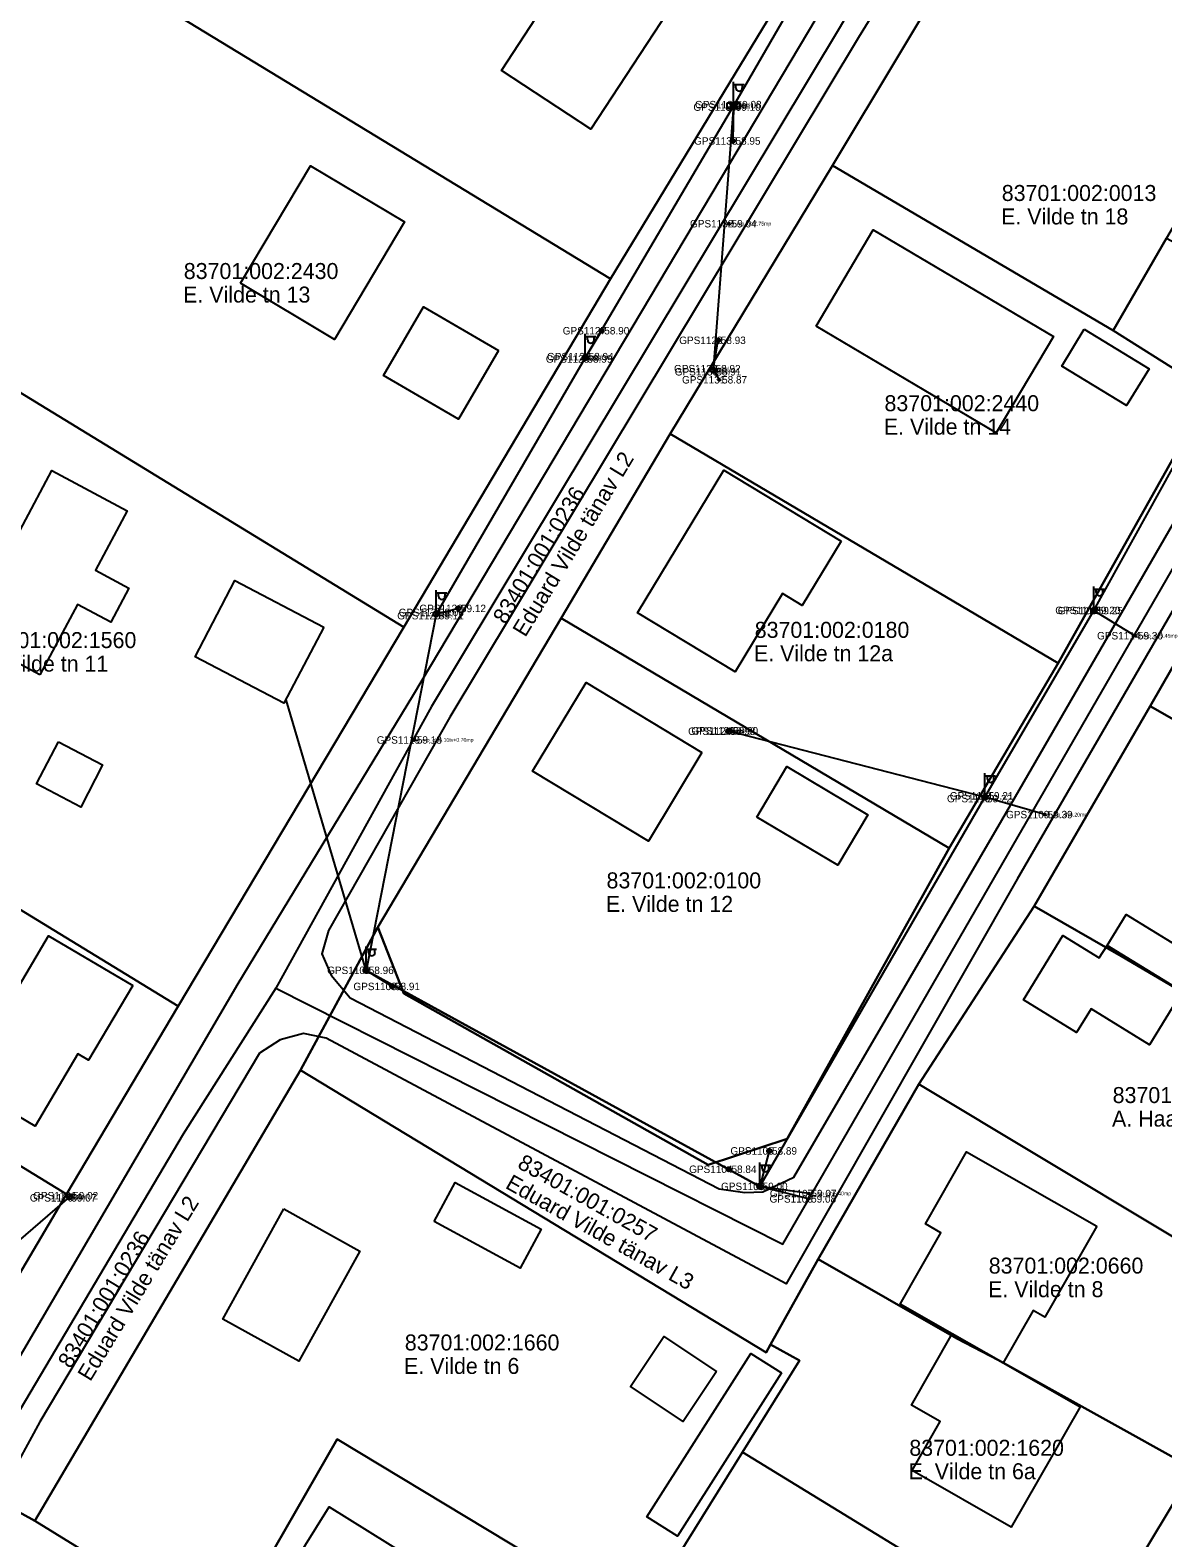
# Model space of a CAD drawing. Extents: x 580119 to 583377, y 6518915 to 6520820.
# Drawn here: x 581695.9 to 581802.2, y 6520085.2 to 6520226.6 of the extents above; entities that cross this region are included whole.
import ezdxf

# ---------------------------------------------------------------- set-up
doc = ezdxf.new("R2010")
doc.units = 0
for name, color, linetype in [('ELRAJATISMP', 7, 'Continuous'), ('Hoone Elu- või ühiskondlik hoone', 7, 'Continuous'), ('Hoone Kõrval- või tootmishoone', 7, 'Continuous'), ('L_AADRESS', 7, 'Continuous'), ('MAAMUDEL', 7, 'Continuous'), ('MOOTKORG-EH2000', 7, 'Continuous'), ('MOOTMPUNKT', 7, 'Continuous'), ('MOOTNR', 7, 'Continuous'), ('MPOHULIIN', 7, 'Continuous'), ('Muu rajatis Katusealune', 7, 'Continuous'), ('PIIR', 7, 'Continuous'), ('POST', 7, 'Continuous'), ('Rippe kõrgus', 7, 'Continuous'), ('SIOHULIIN', 7, 'Continuous'), ('Tee Liiklusala', 7, 'Continuous'), ('Tee Tänav Püsikate', 7, 'Continuous'), ('TUNNUS', 7, 'Continuous')]:
    doc.layers.add(name, color=color, linetype=linetype)

msp = doc.modelspace()

# ---------------------------------------------------------------- linework, layer by layer
at = {"layer": 'ELRAJATISMP'}
for p, q in [((581761.76, 6520219.8), (581761.76, 6520219.21)), ((581762.03, 6520219.8), (581762.03, 6520219.21))]:
    msp.add_line(p, q, dxfattribs=at)
msp.add_lwpolyline([(581761.3, 6520219.8), (581762.5, 6520219.8), (581762.5, 6520219.21), (581761.3, 6520219.21)], close=True, dxfattribs=at)
at = {"layer": 'Hoone Elu- või ühiskondlik hoone'}
for points in [[(581749.32, 6520236.85), (581757.72, 6520231.36), (581748.53, 6520217.33), (581740.14, 6520222.82)], [(581715.66, 6520202.86), (581722.22, 6520213.88), (581731.05, 6520208.63), (581724.5, 6520197.6)], [(581769.66, 6520198.84), (581775.02, 6520207.88), (581791.91, 6520197.86), (581786.55, 6520188.82)], [(581739.87, 6520196.57), (581736.13, 6520190.12), (581729.09, 6520194.21), (581732.84, 6520200.65)], [(581696.86, 6520166.14), (581689.77, 6520169.92), (581697.96, 6520185.31), (581705.05, 6520181.53), (581702.07, 6520175.94), (581705.21, 6520174.27), (581703.51, 6520171.07), (581700.37, 6520172.74)], [(581772.01, 6520178.68), (581768.36, 6520172.63), (581766.51, 6520173.75), (581762.06, 6520166.41), (581752.91, 6520171.95), (581761.01, 6520185.33)], [(581723.47, 6520170.61), (581719.74, 6520163.47), (581711.41, 6520167.83), (581715.14, 6520174.97)], [(581758.95, 6520158.83), (581753.93, 6520150.52), (581743.06, 6520157.09), (581748.09, 6520165.4)], [(581705.56, 6520137), (581701.42, 6520129.98), (581700.4, 6520130.59), (581696.4, 6520123.79), (581688.08, 6520128.69), (581692.34, 6520135.89), (581693.77, 6520135.04), (581697.67, 6520141.65)], [(581795.98, 6520114.4), (581791.1, 6520105.88), (581790, 6520106.5), (581787.19, 6520101.59), (581782.43, 6520104.31), (581777.55, 6520107.1), (581781.37, 6520113.8), (581779.91, 6520114.64), (581783.77, 6520121.38)], [(581719.72, 6520116.03), (581726.86, 6520112.07), (581721.14, 6520101.74), (581714, 6520105.7)], [(581787.19, 6520101.59), (581794.41, 6520097.46), (581787.96, 6520086.18), (581778.67, 6520091.5), (581781.3, 6520096.08), (581778.6, 6520097.63), (581782.43, 6520104.31)], [(581718.35, 6520079.05), (581723.97, 6520088.07), (581737.07, 6520079.91), (581731.45, 6520070.89)]]:
    msp.add_lwpolyline(points, close=True, dxfattribs=at)
at = {"layer": 'Hoone Kõrval- või tootmishoone'}
for points in [[(581794.81, 6520198.55), (581800.89, 6520194.85), (581798.78, 6520191.38), (581792.7, 6520195.08)], [(581764.1, 6520152.79), (581766.91, 6520157.52), (581774.51, 6520153), (581771.7, 6520148.26)], [(581803.99, 6520136.42), (581796.95, 6520140.75), (581798.73, 6520143.64), (581805.77, 6520139.32)], [(581796.95, 6520140.75), (581803.99, 6520136.42), (581800.92, 6520131.43), (581795.45, 6520134.79), (581794.09, 6520132.57), (581789.1, 6520135.64), (581792.8, 6520141.67), (581796.22, 6520139.57)], [(581733.83, 6520114.86), (581735.81, 6520118.5), (581743.87, 6520114.12), (581741.89, 6520110.48)], [(581760.31, 6520100.78), (581757.18, 6520096.08), (581752.24, 6520099.36), (581755.37, 6520104.07)], [(581766.41, 6520100.65), (581756.65, 6520085.34), (581753.77, 6520087.15), (581763.53, 6520102.47)]]:
    msp.add_lwpolyline(points, close=True, dxfattribs=at)
at = {"layer": 'MOOTMPUNKT'}
for centre in [(581761.86, 6520219.39), (581761.94, 6520219.62), (581761.84, 6520216.21), (581761.47, 6520208.45), (581749.53, 6520198.41), (581760.46, 6520197.51), (581747.95, 6520195.76), (581748.06, 6520195.98), (581759.97, 6520194.85), (581760.04, 6520194.56), (581760.58, 6520193.81), (581736.09, 6520172.36), (581795.59, 6520172.18), (581795.82, 6520172.15), (581734.01, 6520171.98), (581734.01, 6520171.68), (581799.58, 6520169.8), (581761.36, 6520160.84), (581761.61, 6520160.88), (581731.95, 6520160.02), (581785.43, 6520154.52), (581785.56, 6520154.78), (581791.11, 6520153.02), (581727.44, 6520138.41), (581729.9, 6520136.9), (581765.26, 6520121.47), (581761.46, 6520119.75), (581699.55, 6520117.07), (581699.72, 6520117.27), (581764.38, 6520118.14), (581768.93, 6520116.97), (581768.96, 6520117.47)]:
    msp.add_circle(centre, 0.1, dxfattribs=at)
at = {"layer": 'MPOHULIIN'}
for p, q in [((581795.71, 6520172.16), (581799.58, 6520169.8)), ((581785.49, 6520154.65), (581761.48, 6520160.86)), ((581791.11, 6520153.02), (581785.49, 6520154.65)), ((581699.63, 6520117.17), (581675.41, 6520096.3)), ((581768.96, 6520117.47), (581764.38, 6520118.14))]:
    msp.add_line(p, q, dxfattribs=at)
for points in [[(581785.93, 6520264.11), (581785.82, 6520260.92), (581761.9, 6520219.5), (581760.01, 6520194.7), (581760.58, 6520193.81)], [(581761.9, 6520219.5), (581748, 6520195.87), (581734.01, 6520171.83), (581727.44, 6520138.41), (581764.38, 6520118.14), (581785.49, 6520154.65), (581795.71, 6520172.16), (581806.94, 6520192.43), (581811.47, 6520190.35)]]:
    msp.add_lwpolyline(points, dxfattribs=at)
at = {"layer": 'Muu rajatis Katusealune'}
msp.add_lwpolyline([(581698.6, 6520159.83), (581702.74, 6520157.68), (581700.68, 6520153.73), (581696.55, 6520155.89)], close=True, dxfattribs=at)
at = {"layer": 'PIIR'}
for points in [[(581696.38, 6520086.78), (581684.97, 6520093.06), (581699.34, 6520117.41), (581709.83, 6520135.06), (581730.99, 6520170.6), (581750.36, 6520203.28), (581768.66, 6520233.42), (581785.75, 6520262.28), (581796.29, 6520255.75), (581771.2, 6520213.92), (581755.98, 6520188.75), (581745.76, 6520171.44), (581728.54, 6520142.46), (581721.29, 6520129.05)], [(581723.58, 6520260.27), (581739.56, 6520251.04), (581768.66, 6520233.42), (581750.36, 6520203.28), (581707.03, 6520229.66)], [(581796.29, 6520255.75), (581821.83, 6520240.08), (581802.53, 6520207.1), (581797.51, 6520198.44), (581771.2, 6520213.92)], [(581689.2, 6520219.3), (581697.63, 6520235.33), (581707.03, 6520229.66), (581750.36, 6520203.28), (581730.99, 6520170.6), (581680.25, 6520201.63)], [(581771.2, 6520213.92), (581797.51, 6520198.44), (581806.64, 6520192.68), (581792.37, 6520167.22), (581755.98, 6520188.75)], [(581764.96, 6520102.57), (581721.29, 6520129.05), (581728.54, 6520142.46), (581730.99, 6520136.24), (581759.52, 6520120.17), (581766.93, 6520122.61), (581782.15, 6520149.87), (581792.37, 6520167.22), (581806.64, 6520192.68), (581797.51, 6520198.44), (581802.53, 6520207.1), (581820.67, 6520197.28), (581812.15, 6520182.64), (581800.99, 6520163.2), (581790.11, 6520144.42), (581779.28, 6520127.73), (581769.84, 6520111.32), (581765.39, 6520103.31)], [(581661.67, 6520164.59), (581666.91, 6520175.02), (581677.87, 6520196.97), (581680.25, 6520201.63), (581730.99, 6520170.6), (581709.83, 6520135.06), (581670.07, 6520159.33)], [(581755.98, 6520188.75), (581792.37, 6520167.22), (581782.15, 6520149.87), (581745.76, 6520171.44)], [(581812.15, 6520182.64), (581846.68, 6520162.43), (581837.68, 6520147.06), (581835.4, 6520143.6), (581800.99, 6520163.2)], [(581728.54, 6520142.46), (581745.76, 6520171.44), (581782.15, 6520149.87), (581766.93, 6520122.61), (581759.52, 6520120.17), (581730.99, 6520136.24)], [(581790.11, 6520144.42), (581800.99, 6520163.2), (581835.4, 6520143.6), (581823.73, 6520125.03), (581804.32, 6520136.18), (581798.27, 6520139.74)], [(581670.07, 6520159.33), (581709.83, 6520135.06), (581699.34, 6520117.41), (581659.64, 6520141.7)], [(581790.11, 6520144.42), (581798.27, 6520139.74), (581804.32, 6520136.18), (581823.73, 6520125.03), (581832.4, 6520118.89), (581829.9, 6520114.5), (581827.55, 6520110.37), (581819.41, 6520115.52), (581813.96, 6520106.91), (581779.28, 6520127.73)], [(581659.64, 6520141.7), (581699.34, 6520117.41), (581684.97, 6520093.06), (581645.42, 6520117.31)], [(581696.38, 6520086.78), (581721.29, 6520129.05), (581764.96, 6520102.57), (581765.39, 6520103.31), (581768.1, 6520101.82), (581762.75, 6520093.2), (581752.93, 6520077.41), (581724.75, 6520094.43), (581714.09, 6520075.87)], [(581779.28, 6520127.73), (581813.96, 6520106.91), (581809.78, 6520099.89), (581805.2, 6520091.6), (581786.76, 6520101.83), (581782.86, 6520103.86), (581769.84, 6520111.32)], [(581768.1, 6520101.82), (581765.39, 6520103.31), (581769.84, 6520111.32), (581782.86, 6520103.86), (581786.76, 6520101.83), (581805.2, 6520091.6), (581803.92, 6520089.68), (581794.38, 6520073.84), (581789.29, 6520076.96), (581762.75, 6520093.2)], [(581724.75, 6520094.43), (581752.93, 6520077.41), (581741.76, 6520059.15), (581714.09, 6520075.87)], [(581752.93, 6520077.41), (581762.75, 6520093.2), (581789.29, 6520076.96), (581768.53, 6520042.82), (581741.76, 6520059.15)], [(581792.34, 6520070.46), (581794.38, 6520073.84), (581803.92, 6520089.68), (581836.47, 6520072.82), (581824.83, 6520050.4), (581803.43, 6520063.65)]]:
    msp.add_lwpolyline(points, close=True, dxfattribs=at)
msp.add_lwpolyline([(581684.97, 6520093.06), (581696.38, 6520086.78), (581714.09, 6520075.87), (581741.76, 6520059.15), (581768.53, 6520042.82), (581786.85, 6520031.7), (581808.31, 6520018.92), (581818.25, 6520012.64), (581847.29, 6519995.61), (581879.39, 6519976.36), (581911.11, 6519957.21), (581942.22, 6519937.53), (581960.1, 6519927.96)], dxfattribs=at)
at = {"layer": 'POST'}
for p, q in [((581761.9, 6520219.75), (581761.9, 6520221.75)), ((581761.9, 6520221.5), (581762.9, 6520221.5)), ((581762.12, 6520221.18), (581762.12, 6520221.5)), ((581762.74, 6520221.18), (581762.74, 6520221.5)), ((581761.9, 6520219.5), (581761.9, 6520219.5)), ((581748, 6520196.12), (581748, 6520198.12)), ((581748, 6520197.87), (581749, 6520197.87)), ((581748.23, 6520197.55), (581748.23, 6520197.87)), ((581748.84, 6520197.55), (581748.84, 6520197.87)), ((581748, 6520195.87), (581748, 6520195.87)), ((581734.01, 6520172.08), (581734.01, 6520174.08)), ((581734.01, 6520173.83), (581735.01, 6520173.83)), ((581734.23, 6520173.51), (581734.23, 6520173.83)), ((581734.85, 6520173.51), (581734.85, 6520173.83)), ((581795.71, 6520172.41), (581795.71, 6520174.41)), ((581795.71, 6520174.16), (581796.71, 6520174.16)), ((581795.93, 6520173.84), (581795.93, 6520174.16)), ((581796.55, 6520173.84), (581796.55, 6520174.16)), ((581734.01, 6520171.83), (581734.01, 6520171.83)), ((581795.71, 6520172.16), (581795.71, 6520172.16)), ((581785.49, 6520154.9), (581785.49, 6520156.9)), ((581785.49, 6520156.65), (581786.49, 6520156.65)), ((581785.72, 6520156.33), (581785.72, 6520156.65)), ((581786.33, 6520156.33), (581786.33, 6520156.65)), ((581785.49, 6520154.65), (581785.49, 6520154.65)), ((581727.44, 6520138.66), (581727.44, 6520140.66)), ((581727.44, 6520140.41), (581728.44, 6520140.41)), ((581727.67, 6520140.09), (581727.67, 6520140.41)), ((581728.28, 6520140.09), (581728.28, 6520140.41)), ((581727.44, 6520138.41), (581727.44, 6520138.41)), ((581764.38, 6520118.39), (581764.38, 6520120.39)), ((581764.38, 6520120.14), (581765.38, 6520120.14)), ((581764.61, 6520119.81), (581764.61, 6520120.14)), ((581765.22, 6520119.81), (581765.22, 6520120.14)), ((581764.38, 6520118.14), (581764.38, 6520118.14))]:
    msp.add_line(p, q, dxfattribs=at)
for points in [[(581761.9, 6520219.5), (581761.84, 6520216.21)], [(581749.53, 6520198.41), (581748, 6520195.87)], [(581760.01, 6520194.7), (581760.46, 6520197.51)], [(581736.09, 6520172.36), (581734.01, 6520171.83)], [(581729.9, 6520136.9), (581727.44, 6520138.41)], [(581765.26, 6520121.47), (581764.38, 6520118.14)], [(581761.46, 6520119.75), (581764.38, 6520118.14)]]:
    msp.add_lwpolyline(points, dxfattribs=at)
for centre, radius in [((581761.9, 6520219.5), 0.25), ((581761.84, 6520216.21), 0.2), ((581749.53, 6520198.41), 0.2), ((581760.46, 6520197.51), 0.2), ((581748, 6520195.87), 0.25), ((581760.01, 6520194.7), 0.25), ((581736.09, 6520172.36), 0.2), ((581795.71, 6520172.16), 0.25), ((581734.01, 6520171.83), 0.25), ((581761.48, 6520160.86), 0.25), ((581785.49, 6520154.65), 0.25), ((581727.44, 6520138.41), 0.25), ((581729.9, 6520136.9), 0.2), ((581765.26, 6520121.47), 0.2), ((581761.46, 6520119.75), 0.2), ((581699.63, 6520117.17), 0.25), ((581764.38, 6520118.14), 0.25)]:
    msp.add_circle(centre, radius, dxfattribs=at)
for centre in [(581762.43, 6520221.18), (581748.54, 6520197.55), (581796.24, 6520173.84), (581734.54, 6520173.51), (581786.03, 6520156.33), (581727.98, 6520140.09), (581764.91, 6520119.81)]:
    msp.add_arc(centre, 0.306, 180, 0, dxfattribs=at)
at = {"layer": 'SIOHULIIN'}
msp.add_lwpolyline([(581768.93, 6520116.97), (581764.38, 6520118.14), (581727.44, 6520138.41), (581719.94, 6520163.78)], dxfattribs=at)
at = {"layer": 'Tee Liiklusala'}
for points in [[(581686.24, 6520286.44), (581655.64, 6520225.53), (581637.04, 6520189.79), (581629.16, 6520173.72), (581611.42, 6520139.03), (581611.36, 6520137.06), (581612.45, 6520134.44), (581613.31, 6520133.17), (581614.79, 6520131.87), (581633.77, 6520120.5), (581683.46, 6520090.37), (581685.52, 6520089.84), (581687.25, 6520090.2), (581689.17, 6520091.86), (581693.63, 6520099.87), (581715.45, 6520137.17), (581731.84, 6520164.16), (581786.24, 6520255.55)], [(581791.12, 6520254.22), (581773.63, 6520225.91), (581735.3, 6520162.16), (581723.93, 6520142.16), (581723.3, 6520139.96), (581724.17, 6520137.95), (581725.95, 6520135.82), (581760.56, 6520117.9), (581762.96, 6520117.57), (581764.66, 6520117.64), (581767.58, 6520119), (581787.09, 6520152.49), (581814.8, 6520200.48), (581816.61, 6520199.5), (581818.38, 6520198.53), (581788.51, 6520146.96), (581766.84, 6520109), (581723.69, 6520132.04), (581721.59, 6520132.47), (581719.38, 6520131.9), (581717.46, 6520130.63), (581696.84, 6520096.06), (581693.74, 6520090.36)]]:
    msp.add_lwpolyline(points, dxfattribs=at)
at = {"layer": 'Tee Tänav Püsikate'}
for points in [[(581794.4, 6520263.72), (581784.99, 6520249.45), (581771.91, 6520226.93), (581733.57, 6520163.16), (581718.97, 6520136.73)], [(581718.97, 6520136.73), (581766.53, 6520112.73), (581816.61, 6520199.5)], [(581718.97, 6520136.73), (581710.29, 6520123.05), (581693.19, 6520094.16), (581687.82, 6520085.01)]]:
    msp.add_lwpolyline(points, dxfattribs=at)

# ---------------------------------------------------------------- texts
at = {"layer": 'L_AADRESS'}
for s, p in [('E. Vilde tn 18', (581787.01, 6520208.38)), ('E. Vilde tn 13', (581710.29, 6520201.05)), ('E. Vilde tn 14', (581776.01, 6520188.66)), ('E. Vilde tn 11', (581691.34, 6520166.43)), ('E. Vilde tn 12a', (581763.83, 6520167.4)), ('E. Vilde tn 12', (581749.94, 6520143.89)), ('A. Haava tn 6', (581797.41, 6520123.75)), ('E. Vilde tn 8', (581785.79, 6520107.75)), ('E. Vilde tn 6', (581731.01, 6520100.55)), ('E. Vilde tn 6a', (581778.33, 6520090.67))]:
    msp.add_text(s, height=1.5, dxfattribs=at).set_placement(p)
for s, rotation, p in [('Eduard Vilde tänav L2', 58.71, (581742.38, 6520169.59)), ('Eduard Vilde tänav L3', 330.6967, (581740.42, 6520118.03)), ('Eduard Vilde tänav L2', 58.71, (581701.58, 6520099.77))]:
    msp.add_text(s, height=1.5, rotation=rotation, dxfattribs=at).set_placement(p)
at = {"layer": 'MAAMUDEL'}
for s, p in [(' kaabel', (581761.86, 6520219.21)), (' kaabel', (581761.94, 6520219.45)), (' kaabel', (581747.95, 6520195.59)), (' kaabel', (581748.06, 6520195.81)), (' kaabel', (581759.97, 6520194.67)), (' kaabel', (581760.04, 6520194.38)), (' kaabel', (581734.01, 6520171.8)), (' kaabel', (581734.01, 6520171.51)), (' kaabel', (581761.36, 6520160.66)), (' kaabel', (581761.61, 6520160.7)), (' kaabel', (581699.55, 6520116.89)), (' kaabel', (581699.72, 6520117.09)), (' si', (581764.38, 6520117.96))]:
    msp.add_text(s, height=0.35, dxfattribs=at).set_placement(p)
at = {"layer": 'MOOTKORG-EH2000'}
for s, p in [(' 59.10', (581761.86, 6520219.04)), (' 59.08', (581761.94, 6520219.27)), (' 58.95', (581761.84, 6520215.86)), (' 59.04', (581761.47, 6520208.1)), (' 58.90', (581749.53, 6520198.06)), (' 58.93', (581760.46, 6520197.16)), (' 58.94', (581748.06, 6520195.63)), (' 58.99', (581747.95, 6520195.41)), (' 58.92', (581759.97, 6520194.5)), (' 58.91', (581760.04, 6520194.21)), (' 58.87', (581760.58, 6520193.46)), (' 59.06', (581734.01, 6520171.63)), (' 59.12', (581736.09, 6520172.01)), (' 59.20', (581795.59, 6520171.83)), (' 59.25', (581795.82, 6520171.8)), (' 59.11', (581734.01, 6520171.33)), (' 59.30', (581799.58, 6520169.45)), (' 58.98', (581761.36, 6520160.49)), (' 58.90', (581761.61, 6520160.53)), (' 59.13', (581731.95, 6520159.67)), (' 59.22', (581785.43, 6520154.17)), (' 59.21', (581785.56, 6520154.43)), (' 59.39', (581791.11, 6520152.67)), (' 58.96', (581727.44, 6520138.06)), (' 58.91', (581729.9, 6520136.55)), (' 58.89', (581765.26, 6520121.12)), (' 58.84', (581761.46, 6520119.4)), (' 59.00', (581764.38, 6520117.79)), (' 59.07', (581699.55, 6520116.72)), (' 59.02', (581699.72, 6520116.92)), (' 59.08', (581768.93, 6520116.62)), (' 59.07', (581768.96, 6520117.12))]:
    msp.add_text(s, height=0.7, dxfattribs=at).set_placement(p)
at = {"layer": 'MOOTNR'}
for s, p in [('GPS1134 ', (581758.15, 6520219.04)), ('GPS1135 ', (581758.3, 6520219.27)), ('GPS1133 ', (581758.21, 6520215.86)), ('GPS1132 ', (581757.83, 6520208.1)), ('GPS1127 ', (581745.89, 6520198.06)), ('GPS1128 ', (581756.82, 6520197.16)), ('GPS1126 ', (581744.42, 6520195.63)), ('GPS1125 ', (581744.31, 6520195.41)), ('GPS1129 ', (581756.33, 6520194.5)), ('GPS1130 ', (581756.4, 6520194.21)), ('GPS1131 ', (581757.08, 6520193.46)), ('GPS1121 ', (581730.51, 6520171.63)), ('GPS1122 ', (581732.45, 6520172.01)), ('GPS1112 ', (581792.09, 6520171.83)), ('GPS1113 ', (581792.32, 6520171.8)), ('GPS1120 ', (581730.37, 6520171.33)), ('GPS1114 ', (581796.01, 6520169.45)), ('GPS1124 ', (581757.65, 6520160.49)), ('GPS1123 ', (581757.97, 6520160.53)), ('GPS1119 ', (581728.45, 6520159.67)), ('GPS1110 ', (581781.93, 6520154.17)), ('GPS1111 ', (581782.2, 6520154.43)), ('GPS1109 ', (581787.47, 6520152.67)), ('GPS1102 ', (581723.8, 6520138.06)), ('GPS1103 ', (581726.26, 6520136.55)), ('GPS1105 ', (581761.62, 6520121.12)), ('GPS1104 ', (581757.75, 6520119.4)), ('GPS1106 ', (581760.74, 6520117.79)), ('GPS1100 ', (581695.91, 6520116.72)), ('GPS1101 ', (581696.22, 6520116.92)), ('GPS1108 ', (581765.29, 6520116.62)), ('GPS1107 ', (581765.32, 6520117.12))]:
    msp.add_text(s, height=0.7, dxfattribs=at).set_placement(p)
at = {"layer": 'Rippe kõrgus'}
for s, p in [(' el_mp_ohl7.75mp', (581761.47, 6520208.28)), (' el_mp_ohl5.45mp', (581799.58, 6520169.62)), (' el_mp_ohl5.10tv+0.70mp', (581731.95, 6520159.85)), (' el_mp_ohl6.20mp', (581791.11, 6520152.84)), (' el_mp_ohl6.40mp', (581768.96, 6520117.3))]:
    msp.add_text(s, height=0.35, dxfattribs=at).set_placement(p)
at = {"layer": 'TUNNUS'}
for s, p in [('83701:002:0013', (581787.07, 6520210.58)), ('83701:002:2430', (581710.35, 6520203.26)), ('83701:002:2440', (581776.07, 6520190.86)), ('83701:002:0180', (581763.9, 6520169.6)), ('83701:002:1560', (581691.4, 6520168.64)), ('83701:002:0100', (581750, 6520146.1)), ('83701:002:1430', (581797.47, 6520125.96)), ('83701:002:0660', (581785.85, 6520109.96)), ('83701:002:1660', (581731.08, 6520102.75)), ('83701:002:1620', (581778.4, 6520092.87))]:
    msp.add_text(s, height=1.5, dxfattribs=at).set_placement(p)
for s, rotation, p in [('83401:001:0236', 58.71, (581740.53, 6520170.79)), ('83401:001:0257', 330.6967, (581741.55, 6520119.93)), ('83401:001:0236', 58.71, (581699.73, 6520100.97))]:
    msp.add_text(s, height=1.5, rotation=rotation, dxfattribs=at).set_placement(p)

doc.saveas('drawing.dxf')
